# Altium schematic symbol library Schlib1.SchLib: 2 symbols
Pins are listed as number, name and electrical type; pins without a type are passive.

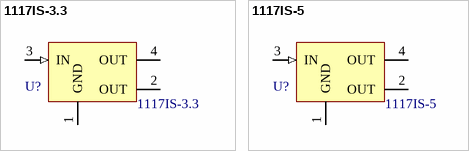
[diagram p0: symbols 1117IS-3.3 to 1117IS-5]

## 1117IS-3.3
designator U?
footprint SOT223_N (Footprint not found)
pins: 1 GND, 2 OUT, 3 IN (in), 4 OUT

## 1117IS-5
designator U?
footprint SOT223_N (Footprint not found)
pins: 1 GND, 2 OUT, 3 IN (in), 4 OUT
